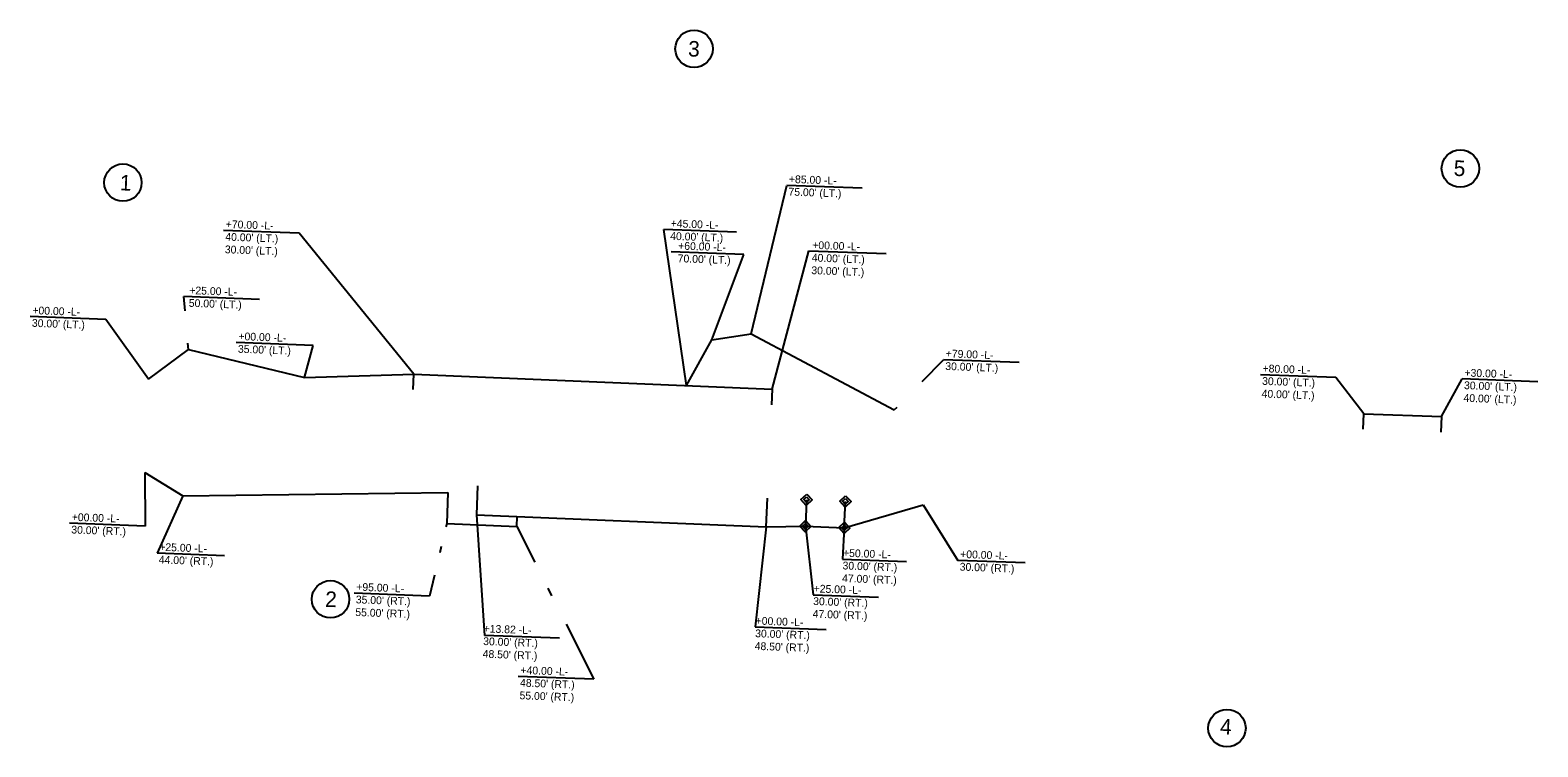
# Model space of a CAD drawing. Extents: x 2170626 to 2171594, y 723877 to 724337.
import ezdxf

# ---------------------------------------------------------------- set-up
doc = ezdxf.new("R2010")
doc.units = 0
for name, color, linetype in [('Prop Easement Construction', 7, 'Continuous'), ('Prop Easement Construction Station Offsets', 7, 'Continuous'), ('Prop Easement Permanent Drainage', 7, 'Continuous'), ('Prop Easement Permanent Drainage Station Offsets', 7, 'Continuous'), ('Prop Easement Temporary Drainage', 7, 'Continuous'), ('Prop Easement Temporary Drainage Station Offsets', 7, 'Continuous'), ('Prop Parcel Number CELL', 7, 'Continuous'), ('Prop Parcel Number Text', 7, 'Continuous'), ('Prop ROW Marker CELL', 7, 'Continuous'), ('Prop ROW Permanent Easement CELL', 7, 'Continuous')]:
    doc.layers.add(name, color=color, linetype=linetype)

msp = doc.modelspace()

# ---------------------------------------------------------------- linework, layer by layer
at = {"layer": 'Prop Easement Construction'}
for p, q in [((2171047.37, 724109.24), (2171063.62, 724138.58)), ((2171063.62, 724138.58), (2171088.81, 724142.52)), ((2170702.13, 724113.41), (2170727.9, 724132.43)), ((2170727.9, 724132.43), (2170802.3, 724114.47)), ((2170802.3, 724114.47), (2170872.49, 724116.61)), ((2171481.43, 724081.19), (2171481.8, 724091.18)), ((2171481.8, 724091.18), (2171531.69, 724089.36)), ((2171531.69, 724089.36), (2171531.33, 724079.37)), ((2170699.81, 724053.46), (2170724.23, 724038.4)), ((2170724.23, 724038.4), (2170894.35, 724040.63)), ((2170894.35, 724040.63), (2170893.51, 724020.65)), ((2171148.6, 724017.89), (2171199.28, 724032.76)), ((2170893.51, 724020.65), (2170938.45, 724018.75)), ((2170938.45, 724018.75), (2170938.73, 724025.25)), ((2171098.58, 724018.5), (2171123.62, 724018.94))]:
    msp.add_line(p, q, dxfattribs=at)
msp.add_lwpolyline([(2171088.81, 724142.52), (2171180.67, 724093.6)], dxfattribs=at)
at = {"layer": 'Prop Easement Construction Station Offsets'}
for p, q in [((2171088.81, 724142.52), (2171111.65, 724237.74)), ((2171160.15, 724235.93), (2171111.65, 724237.74)), ((2171047.37, 724109.24), (2171032.74, 724209.41)), ((2171079.38, 724207.66), (2171032.74, 724209.41)), ((2171084.19, 724193.31), (2171037.55, 724195.06)), ((2171063.62, 724138.58), (2171084.19, 724193.31)), ((2170773.47, 724164.57), (2170724.97, 724166.39)), ((2170725.76, 724157.23), (2170724.97, 724166.39)), ((2170674.79, 724151.66), (2170626.3, 724153.48)), ((2170702.13, 724113.41), (2170674.79, 724151.66)), ((2170727.9, 724132.43), (2170727.56, 724136.37)), ((2170807.92, 724134.98), (2170758.49, 724136.83)), ((2170802.3, 724114.47), (2170807.92, 724134.98)), ((2171198.6, 724111.86), (2171212.26, 724125.76)), ((2171260.75, 724123.95), (2171212.26, 724125.76)), ((2171464, 724114.4), (2171415.51, 724116.21)), ((2171481.8, 724091.18), (2171464, 724114.4)), ((2171531.69, 724089.36), (2171545.04, 724113.46)), ((2171593.53, 724111.64), (2171545.04, 724113.46)), ((2171180.67, 724093.6), (2171182.43, 724095.4)), ((2170699.81, 724053.46), (2170700.06, 724018.98)), ((2170724.23, 724038.4), (2170707.7, 724001.56)), ((2171199.28, 724032.76), (2171221.51, 723996.96)), ((2170700.06, 724018.98), (2170651.57, 724020.8)), ((2170893.51, 724020.65), (2170893, 724018.48)), ((2170938.45, 724018.75), (2170949.98, 723995.9)), ((2170751.07, 723999.94), (2170707.7, 724001.56)), ((2170890.07, 724006.01), (2170889.08, 724001.81)), ((2171264.64, 723995.35), (2171221.51, 723996.96)), ((2170885.72, 723987.5), (2170882.57, 723974.12)), ((2170882.57, 723974.12), (2170834.08, 723975.93)), ((2170958.39, 723979.23), (2170960.85, 723974.36)), ((2170970.1, 723956.01), (2170987.92, 723920.69)), ((2170987.92, 723920.69), (2170939.43, 723922.51))]:
    msp.add_line(p, q, dxfattribs=at)
at = {"layer": 'Prop Easement Permanent Drainage'}
for p, q in [((2171124.34, 724035.93), (2171123.62, 724018.94)), ((2171148.6, 724017.89), (2171149.32, 724034.87)), ((2171123.62, 724018.94), (2171148.6, 724017.89))]:
    msp.add_line(p, q, dxfattribs=at)
at = {"layer": 'Prop Easement Permanent Drainage Station Offsets'}
for p, q in [((2171123.62, 724018.94), (2171128.54, 723974.97)), ((2171148.6, 724017.89), (2171147.39, 723997.83)), ((2171147.39, 723997.83), (2171188.52, 723996.29)), ((2171128.54, 723974.97), (2171170.51, 723973.4))]:
    msp.add_line(p, q, dxfattribs=at)
at = {"layer": 'Prop Easement Temporary Drainage'}
for p, q in [((2170872.08, 724106.61), (2170872.49, 724116.61)), ((2170872.49, 724116.61), (2171102.32, 724106.92)), ((2171102.32, 724106.92), (2171101.89, 724096.93)), ((2170913.35, 724044.83), (2170912.57, 724026.35)), ((2171098.58, 724018.5), (2171099.36, 724036.98)), ((2170912.57, 724026.35), (2171098.58, 724018.5))]:
    msp.add_line(p, q, dxfattribs=at)
at = {"layer": 'Prop Easement Temporary Drainage Station Offsets'}
for p, q in [((2170798.87, 724207), (2170750.37, 724208.81)), ((2170872.49, 724116.61), (2170798.87, 724207)), ((2171102.32, 724106.92), (2171125.84, 724195.81)), ((2171125.84, 724195.81), (2171175.4, 724193.95)), ((2170912.57, 724026.35), (2170917.77, 723948.84)), ((2171098.58, 724018.5), (2171091.33, 723954.3)), ((2171091.33, 723954.3), (2171136.89, 723952.59)), ((2170965.84, 723947.04), (2170917.77, 723948.84))]:
    msp.add_line(p, q, dxfattribs=at)
at = {"layer": 'Prop Parcel Number CELL'}
for p, q in [((2171052.19, 724325.41), (2171052.19, 724325.41)), ((2171543.83, 724248.57), (2171543.83, 724248.57)), ((2170685.83, 724239.51), (2170685.83, 724239.51)), ((2170819.01, 723972.07), (2170819.01, 723972.07)), ((2171394.11, 723889.3), (2171394.11, 723889.3))]:
    msp.add_line(p, q, dxfattribs=at)
for centre in [(2171052.19, 724325.41), (2171543.83, 724248.57), (2170685.83, 724239.51), (2170819.01, 723972.07), (2171394.11, 723889.3)]:
    msp.add_circle(centre, 12, dxfattribs=at)
at = {"layer": 'Prop ROW Marker CELL'}
for p, q in [((2171124.34, 724035.93), (2171124.34, 724035.93)), ((2171149.32, 724034.87), (2171149.32, 724034.87)), ((2171123.62, 724018.94), (2171123.62, 724018.94)), ((2171148.6, 724017.89), (2171148.6, 724017.89))]:
    msp.add_line(p, q, dxfattribs=at)
at = {"layer": 'Prop ROW Permanent Easement CELL'}
for points in [[(2171124.48, 724039.52), (2171127.94, 724035.79), (2171124.21, 724032.33), (2171120.74, 724036.06)], [(2171124.41, 724037.72), (2171126.14, 724035.86), (2171124.27, 724034.13), (2171122.54, 724035.99)], [(2171149.45, 724038.47), (2171152.92, 724034.74), (2171149.19, 724031.28), (2171145.72, 724035.01)], [(2171149.39, 724036.67), (2171151.12, 724034.8), (2171149.25, 724033.07), (2171147.52, 724034.94)], [(2171123.76, 724022.54), (2171127.22, 724018.81), (2171123.49, 724015.35), (2171120.03, 724019.08)], [(2171123.69, 724020.74), (2171125.42, 724018.87), (2171123.56, 724017.14), (2171121.83, 724019.01)], [(2171148.74, 724021.49), (2171152.2, 724017.75), (2171148.47, 724014.29), (2171145.01, 724018.02)], [(2171148.67, 724019.69), (2171150.4, 724017.82), (2171148.54, 724016.09), (2171146.8, 724017.95)]]:
    msp.add_lwpolyline(points, close=True, dxfattribs=at)

# ---------------------------------------------------------------- texts
at = {"layer": 'Prop Easement Construction Station Offsets'}
for s, p in [('+85.00 -L-', (2171113, 724239.38)), ("75.00' (LT.)", (2171112.7, 724231.27)), ('+45.00 -L-', (2171037.15, 724210.94)), ("40.00' (LT.)", (2171036.84, 724202.82)), ('+60.00 -L-', (2171041.95, 724196.59)), ("70.00' (LT.)", (2171041.65, 724188.47)), ('+25.00 -L-', (2170728.31, 724167.96)), ('+00.00 -L-', (2170627.65, 724155.12)), ("50.00' (LT.)", (2170728.01, 724159.84)), ("30.00' (LT.)", (2170627.35, 724147)), ('+00.00 -L-', (2170759.84, 724138.47)), ("35.00' (LT.)", (2170759.53, 724130.35)), ('+79.00 -L-', (2171213.61, 724127.41)), ("30.00' (LT.)", (2171213.3, 724119.29)), ('+80.00 -L-', (2171416.86, 724117.86)), ('+30.00 -L-', (2171546.39, 724115.1)), ("30.00' (LT.)", (2171416.56, 724109.74)), ("30.00' (LT.)", (2171546.09, 724106.98)), ("40.00' (LT.)", (2171416.25, 724101.62)), ("40.00' (LT.)", (2171545.78, 724098.87)), ('+00.00 -L-', (2170652.92, 724022.44)), ("30.00' (RT.)", (2170652.62, 724014.32)), ('+25.00 -L-', (2170709.05, 724003.2)), ('+00.00 -L-', (2171222.86, 723998.61)), ("44.00' (RT.)", (2170708.75, 723995.08)), ("30.00' (RT.)", (2171222.56, 723990.49)), ('+95.00 -L-', (2170835.43, 723977.58)), ("35.00' (RT.)", (2170835.13, 723969.46)), ("55.00' (RT.)", (2170834.82, 723961.34)), ('+40.00 -L-', (2170940.78, 723924.15)), ("48.50' (RT.)", (2170940.48, 723916.03)), ("55.00' (RT.)", (2170940.18, 723907.91))]:
    msp.add_text(s, height=5, rotation=357.85741, dxfattribs=at).set_placement(p)
at = {"layer": 'Prop Easement Permanent Drainage Station Offsets'}
for s, p in [('+50.00 -L-', (2171147.71, 723999.38)), ("30.00' (RT.)", (2171147.41, 723991.26)), ("47.00' (RT.)", (2171147.1, 723983.14)), ("30.00' (RT.)", (2171128.56, 723968.4)), ('+25.00 -L-', (2171128.86, 723976.52)), ("47.00' (RT.)", (2171128.26, 723960.28))]:
    msp.add_text(s, height=5, rotation=357.85741, dxfattribs=at).set_placement(p)
at = {"layer": 'Prop Easement Temporary Drainage Station Offsets'}
for s, p in [('+70.00 -L-', (2170751.72, 724210.46)), ("40.00' (LT.)", (2170751.42, 724202.34)), ("30.00' (LT.)", (2170751.12, 724194.22)), ('+00.00 -L-', (2171127.98, 724197.04)), ("30.00' (LT.)", (2171127.37, 724180.81)), ("40.00' (LT.)", (2171127.67, 724188.92)), ('+13.82 -L-', (2170917.16, 723950.82)), ("30.00' (RT.)", (2171091.35, 723947.73)), ('+00.00 -L-', (2171091.65, 723955.85)), ("30.00' (RT.)", (2170916.86, 723942.7)), ("48.50' (RT.)", (2171091.04, 723939.61)), ("48.50' (RT.)", (2170916.55, 723934.58))]:
    msp.add_text(s, height=5, rotation=357.85741, dxfattribs=at).set_placement(p)
at = {"layer": 'Prop Parcel Number Text'}
for s, p in [('3', (2171048.27, 724320.55)), ('5', (2171539.41, 724243.89)), ('1', (2170683.67, 724234.59)), ('2', (2170815.42, 723967.21)), ('4', (2171389.52, 723885.41))]:
    msp.add_text(s, height=10, rotation=357.85741, dxfattribs=at).set_placement(p)

doc.saveas('drawing.dxf')
